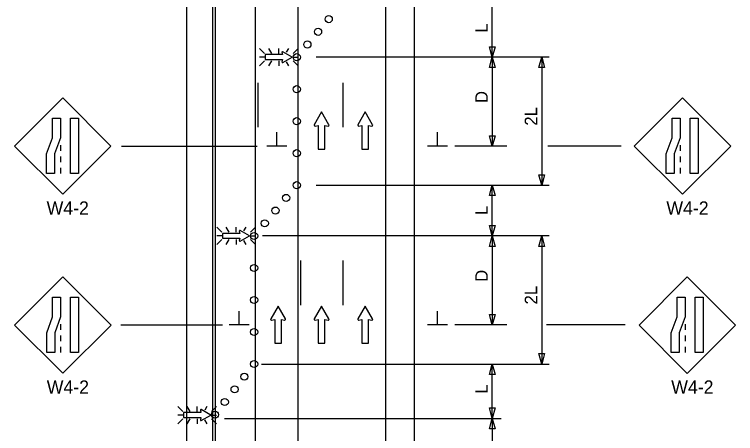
# Model space of a CAD drawing. Extents: x 16726 to 18475, y 5752 to 6929.
# Drawn here: x 16770.6 to 17176.3, y 6401.3 to 6637.1 of the extents above; entities that cross this region are included whole.
import ezdxf

# ---------------------------------------------------------------- set-up
doc = ezdxf.new("R2010")
doc.units = 0
for name, color, linetype in [('ALI_LEGAL_EX', 7, 'Continuous'), ('MT_SCRATCH_LEVEL_E', 7, 'Continuous'), ('PAVT_EDGE_EX', 7, 'Continuous'), ('TRAFFIC_SIGNS_PR', 7, 'Continuous'), ('TYPICAL_TEXT_DIMEN_PR', 7, 'Continuous')]:
    doc.layers.add(name, color=color, linetype=linetype)

msp = doc.modelspace()

# ---------------------------------------------------------------- linework, layer by layer
at = {"layer": 'ALI_LEGAL_EX'}
for p, q in [((16881.97, 6876.43), (16881.97, 5996.39)), ((16905.97, 6876.43), (16905.97, 5996.39)), ((16929.97, 6876.43), (16929.97, 5996.39))]:
    msp.add_line(p, q, dxfattribs=at)
for points in [[(16907.45, 6598.64), (16907.45, 6573.64)], [(16955.45, 6598.64), (16955.45, 6573.64)], [(16931.45, 6498.64), (16931.45, 6473.64)], [(16955.45, 6498.64), (16955.45, 6473.64)]]:
    msp.add_lwpolyline(points, dxfattribs=at)
at = {"layer": 'MT_SCRATCH_LEVEL_E'}
for p, q in [((16943.41, 6582.24), (16939.3, 6575)), ((16947.56, 6575), (16943.41, 6582.24)), ((16967.97, 6582.24), (16963.86, 6575)), ((16972.12, 6575), (16967.97, 6582.24)), ((16939.79, 6574.31), (16941.56, 6574.63)), ((16941.56, 6574.63), (16941.56, 6561.37)), ((16945.3, 6561.37), (16945.3, 6574.63)), ((16945.3, 6574.63), (16947.08, 6574.31)), ((16964.34, 6574.31), (16966.12, 6574.63)), ((16966.12, 6574.63), (16966.12, 6561.37)), ((16969.86, 6561.37), (16969.86, 6574.63)), ((16969.86, 6574.63), (16971.64, 6574.31)), ((16941.56, 6561.37), (16945.3, 6561.37)), ((16966.12, 6561.37), (16969.86, 6561.37)), ((16918.89, 6473.07), (16914.77, 6465.83)), ((16923.03, 6465.83), (16918.89, 6473.07)), ((16943.41, 6473.07), (16939.3, 6465.83)), ((16947.56, 6465.83), (16943.41, 6473.07)), ((16967.97, 6473.07), (16963.86, 6465.83)), ((16972.12, 6465.83), (16967.97, 6473.07)), ((16915.26, 6465.15), (16917.03, 6465.46)), ((16917.03, 6465.46), (16917.03, 6452.2)), ((16920.78, 6452.2), (16920.78, 6465.46)), ((16920.78, 6465.46), (16922.55, 6465.15)), ((16939.79, 6465.15), (16941.56, 6465.46)), ((16941.56, 6465.46), (16941.56, 6452.2)), ((16945.3, 6452.2), (16945.3, 6465.46)), ((16945.3, 6465.46), (16947.08, 6465.15)), ((16964.34, 6465.15), (16966.12, 6465.46)), ((16966.12, 6465.46), (16966.12, 6452.2)), ((16969.86, 6452.2), (16969.86, 6465.46)), ((16969.86, 6465.46), (16971.64, 6465.15)), ((16917.03, 6452.2), (16920.78, 6452.2)), ((16941.56, 6452.2), (16945.3, 6452.2)), ((16966.12, 6452.2), (16969.86, 6452.2))]:
    msp.add_line(p, q, dxfattribs=at)
for centre, start, end in [((16939.71, 6574.77), 150.4248, 279.9638), ((16947.15, 6574.77), 260.0362, 29.7731), ((16964.27, 6574.77), 150.4248, 279.9638), ((16971.71, 6574.77), 260.0362, 29.7731), ((16915.18, 6465.6), 150.4248, 279.9638), ((16922.62, 6465.61), 260.0362, 29.7731), ((16939.71, 6465.6), 150.4248, 279.9638), ((16947.15, 6465.61), 260.0362, 29.7731), ((16964.27, 6465.6), 150.4248, 279.9638), ((16971.71, 6465.61), 260.0362, 29.7731)]:
    msp.add_arc(centre, 0.463, start, end, dxfattribs=at)
at = {"layer": 'PAVT_EDGE_EX'}
for p, q in [((16867.45, 6928.88), (16867.45, 6018.6)), ((16883.45, 6928.88), (16883.45, 6018.6)), ((16979.45, 6928.88), (16979.45, 6018.6)), ((16995.45, 6928.88), (16995.45, 6018.6))]:
    msp.add_line(p, q, dxfattribs=at)
at = {"layer": 'TRAFFIC_SIGNS_PR'}
for p, q in [((16911.22, 6615.13), (16908.4, 6617.95)), ((16913.52, 6617.95), (16915.15, 6615.13)), ((16919.31, 6615.13), (16919.31, 6617.95)), ((16924.78, 6617.95), (16923.57, 6615.86)), ((16930.21, 6617.95), (16927.39, 6615.13)), ((16911.22, 6613.1), (16908.4, 6613.1)), ((16927.39, 6613.1), (16930.21, 6613.1)), ((16911.22, 6611.07), (16908.4, 6608.25)), ((16915.17, 6611.07), (16913.54, 6608.25)), ((16919.31, 6611.07), (16919.31, 6608.25)), ((16923.49, 6610.43), (16924.75, 6608.25)), ((16930.21, 6608.25), (16927.39, 6611.07)), ((16797.77, 6590.23), (16770.62, 6563.08)), ((16824.92, 6563.08), (16797.77, 6590.23)), ((17146.4, 6590.23), (17119.25, 6563.08)), ((17173.55, 6563.08), (17146.4, 6590.23)), ((16770.62, 6563.08), (16797.77, 6535.92)), ((16796.52, 6563.57), (16796.52, 6560.37)), ((16797.77, 6535.92), (16824.92, 6563.08)), ((17119.25, 6563.08), (17146.4, 6535.92)), ((17145.15, 6563.57), (17145.15, 6560.37)), ((17146.4, 6535.92), (17173.55, 6563.08)), ((16796.52, 6557.17), (16796.52, 6553.97)), ((17145.15, 6557.17), (17145.15, 6553.97)), ((16796.52, 6550.77), (16796.52, 6547.57)), ((17145.15, 6550.77), (17145.15, 6547.57)), ((16887.22, 6514.57), (16884.4, 6517.39)), ((16889.52, 6517.39), (16891.15, 6514.57)), ((16895.31, 6514.57), (16895.31, 6517.39)), ((16900.78, 6517.39), (16899.57, 6515.3)), ((16906.21, 6517.39), (16903.39, 6514.57)), ((16887.22, 6512.54), (16884.4, 6512.54)), ((16903.39, 6512.54), (16906.21, 6512.54)), ((16887.22, 6510.51), (16884.4, 6507.69)), ((16891.17, 6510.51), (16889.54, 6507.69)), ((16895.31, 6510.51), (16895.31, 6507.69)), ((16899.49, 6509.87), (16900.75, 6507.69)), ((16906.21, 6507.69), (16903.39, 6510.51)), ((16797.85, 6489.53), (16770.69, 6462.38)), ((16825, 6462.38), (16797.85, 6489.53)), ((17149.14, 6489.52), (17121.98, 6462.37)), ((17176.29, 6462.37), (17149.14, 6489.52)), ((16770.69, 6462.38), (16797.85, 6435.23)), ((16796.6, 6462.87), (16796.6, 6459.67)), ((16797.85, 6435.23), (16825, 6462.38)), ((17121.98, 6462.37), (17149.14, 6435.21)), ((17147.89, 6462.86), (17147.89, 6459.66)), ((17149.14, 6435.21), (17176.29, 6462.37)), ((16796.6, 6456.47), (16796.6, 6453.27)), ((17147.89, 6456.46), (17147.89, 6453.26)), ((16796.6, 6450.07), (16796.6, 6446.87)), ((17147.89, 6450.06), (17147.89, 6446.86)), ((16865.3, 6413.78), (16862.48, 6416.6)), ((16867.6, 6416.6), (16869.23, 6413.78)), ((16873.39, 6413.78), (16873.39, 6416.6)), ((16878.85, 6416.6), (16877.65, 6414.51)), ((16884.29, 6416.6), (16881.47, 6413.78)), ((16865.3, 6411.75), (16862.48, 6411.75)), ((16865.3, 6409.72), (16862.48, 6406.89)), ((16869.25, 6409.72), (16867.62, 6406.9)), ((16873.39, 6409.72), (16873.39, 6406.9)), ((16881.47, 6411.75), (16884.29, 6411.75)), ((16884.29, 6406.9), (16881.47, 6409.72)), ((16877.57, 6409.08), (16878.83, 6406.9))]:
    msp.add_line(p, q, dxfattribs=at)
for points in [[(16921.13, 6615.78), (16921.36, 6614.49), (16911.64, 6614.49), (16911.64, 6611.74), (16921.36, 6611.74), (16921.13, 6610.44)], [(16921.63, 6610.09), (16926.94, 6613.1), (16921.63, 6616.14)], [(16897.13, 6515.22), (16897.36, 6513.92), (16887.64, 6513.92), (16887.64, 6511.18), (16897.36, 6511.18), (16897.13, 6509.88)], [(16897.63, 6509.52), (16902.94, 6512.54), (16897.63, 6515.58)], [(16875.21, 6414.43), (16875.44, 6413.13), (16865.72, 6413.13), (16865.72, 6410.39), (16875.44, 6410.39), (16875.21, 6409.09)], [(16875.71, 6408.73), (16881.02, 6411.75), (16875.71, 6414.79)]]:
    msp.add_lwpolyline(points, dxfattribs=at)
for points in [[(16796.52, 6578.81), (16796.52, 6567.63), (16793.18, 6558.75), (16793.18, 6547.57), (16788.68, 6547.57), (16788.68, 6558.75), (16792.03, 6567.63), (16792.03, 6578.81)], [(16806.66, 6578.81), (16806.66, 6547.57), (16802.16, 6547.57), (16802.16, 6578.81)], [(17145.15, 6578.81), (17145.15, 6567.63), (17141.81, 6558.75), (17141.81, 6547.57), (17137.31, 6547.57), (17137.31, 6558.75), (17140.66, 6567.63), (17140.66, 6578.81)], [(17155.29, 6578.81), (17155.29, 6547.57), (17150.8, 6547.57), (17150.8, 6578.81)], [(16796.6, 6478.12), (16796.6, 6466.93), (16793.26, 6458.05), (16793.26, 6446.87), (16788.76, 6446.87), (16788.76, 6458.05), (16792.11, 6466.93), (16792.11, 6478.12)], [(16806.74, 6478.12), (16806.74, 6446.87), (16802.24, 6446.87), (16802.24, 6478.12)], [(17147.89, 6478.1), (17147.89, 6466.92), (17144.54, 6458.04), (17144.54, 6446.86), (17140.05, 6446.86), (17140.05, 6458.04), (17143.4, 6466.92), (17143.4, 6478.1)], [(17158.02, 6478.1), (17158.02, 6446.86), (17153.53, 6446.86), (17153.53, 6478.1)]]:
    msp.add_lwpolyline(points, close=True, dxfattribs=at)
for centre in [(16947.45, 6634.45), (16941.45, 6627.31), (16935.45, 6620.17), (16929.45, 6613.03), (16929.45, 6595.03), (16929.45, 6577.03), (16929.45, 6559.03), (16929.45, 6541.03), (16923.45, 6533.89), (16917.45, 6526.75), (16911.45, 6519.61), (16905.45, 6512.47), (16905.45, 6494.47), (16905.45, 6476.47), (16905.45, 6458.47), (16905.45, 6440.47), (16899.95, 6433.33), (16894.45, 6426.21), (16888.95, 6419.08), (16883.46, 6411.96)]:
    msp.add_circle(centre, 2, dxfattribs=at)
for centre, start, end in [((16921.47, 6615.84), 61.4833, 189.9593), ((16921.47, 6610.39), 170.7308, 298.8916), ((16897.47, 6515.28), 61.4833, 189.9593), ((16897.47, 6509.82), 170.7308, 298.8916), ((16875.55, 6414.49), 61.4833, 189.9593), ((16875.55, 6409.03), 170.7308, 298.8916)]:
    msp.add_arc(centre, 0.341, start, end, dxfattribs=at)
at = {"layer": 'TYPICAL_TEXT_DIMEN_PR'}
for p, q in [((17039.45, 6613.03), (17039.45, 6643.59)), ((17039.45, 6613.03), (17037.88, 6618.89)), ((17037.88, 6618.89), (17039.45, 6618.89)), ((17039.45, 6618.89), (17041.02, 6618.89)), ((17041.02, 6618.89), (17039.45, 6613.03)), ((17071.49, 6613.03), (16940.35, 6613.03)), ((17037.88, 6607.17), (17039.45, 6613.03)), ((17039.45, 6613.03), (17039.45, 6563.03)), ((17039.45, 6613.03), (17041.02, 6607.17)), ((17065.68, 6607.17), (17067.25, 6613.03)), ((17067.25, 6613.03), (17068.82, 6607.17)), ((17067.25, 6613.03), (17067.25, 6541.03)), ((17039.45, 6607.17), (17037.88, 6607.17)), ((17041.02, 6607.17), (17039.45, 6607.17)), ((17067.25, 6607.17), (17065.68, 6607.17)), ((17068.82, 6607.17), (17067.25, 6607.17)), ((16918.24, 6563.03), (16918.24, 6570.82)), ((17008.57, 6563.03), (17008.57, 6570.82)), ((17039.45, 6563.03), (17037.88, 6568.89)), ((17037.88, 6568.89), (17039.45, 6568.89)), ((17039.45, 6568.89), (17041.02, 6568.89)), ((17041.02, 6568.89), (17039.45, 6563.03)), ((17067.25, 6567.9), (17067.25, 6564.13)), ((16830.86, 6563.03), (16907.2, 6563.03)), ((16923.87, 6563.03), (16912.62, 6563.03)), ((17014.2, 6563.03), (17002.95, 6563.03)), ((17047.58, 6563.03), (17018.45, 6563.03)), ((17112, 6563.03), (17070.65, 6563.03)), ((17067.25, 6541.03), (17065.68, 6546.89)), ((17065.68, 6546.89), (17067.25, 6546.89)), ((17067.25, 6546.89), (17068.82, 6546.89)), ((17068.82, 6546.89), (17067.25, 6541.03)), ((16940.35, 6541.03), (17071.49, 6541.03)), ((17037.88, 6535.17), (17039.45, 6541.03)), ((17039.45, 6512.47), (17039.45, 6541.03)), ((17039.45, 6541.03), (17041.02, 6535.17)), ((17039.45, 6535.17), (17037.88, 6535.17)), ((17041.02, 6535.17), (17039.45, 6535.17)), ((17039.45, 6512.47), (17037.88, 6518.33)), ((17037.88, 6518.33), (17039.45, 6518.33)), ((17039.45, 6518.33), (17041.02, 6518.33)), ((17041.02, 6518.33), (17039.45, 6512.47)), ((17071.49, 6512.47), (16910.16, 6512.47)), ((17037.88, 6506.61), (17039.45, 6512.47)), ((17039.45, 6512.47), (17039.45, 6462.47)), ((17039.45, 6512.47), (17041.02, 6506.61)), ((17065.68, 6506.61), (17067.25, 6512.47)), ((17067.25, 6512.47), (17068.82, 6506.61)), ((17067.25, 6512.47), (17067.25, 6440.47)), ((17039.45, 6506.61), (17037.88, 6506.61)), ((17041.02, 6506.61), (17039.45, 6506.61)), ((17067.25, 6506.61), (17065.68, 6506.61)), ((17068.82, 6506.61), (17067.25, 6506.61)), ((16897.08, 6462.47), (16897.08, 6470.25)), ((17008.57, 6462.47), (17008.57, 6470.25)), ((17039.45, 6462.47), (17037.88, 6468.33)), ((17037.88, 6468.33), (17039.45, 6468.33)), ((17039.45, 6468.33), (17041.02, 6468.33)), ((17041.02, 6468.33), (17039.45, 6462.47)), ((17067.25, 6467.34), (17067.25, 6463.57)), ((16830.5, 6462.47), (16887.64, 6462.47)), ((16902.71, 6462.47), (16891.46, 6462.47)), ((17014.2, 6462.47), (17002.95, 6462.47)), ((17047.58, 6462.47), (17018.45, 6462.47)), ((17114.15, 6462.47), (17069.93, 6462.47)), ((17067.25, 6440.47), (17065.68, 6446.33)), ((17065.68, 6446.33), (17067.25, 6446.33)), ((17067.25, 6446.33), (17068.82, 6446.33)), ((17068.82, 6446.33), (17067.25, 6440.47)), ((16909.63, 6440.47), (17071.49, 6440.47)), ((17037.88, 6434.61), (17039.45, 6440.47)), ((17039.45, 6409.9), (17039.45, 6440.47)), ((17039.45, 6440.47), (17041.02, 6434.61)), ((17039.45, 6434.61), (17037.88, 6434.61)), ((17041.02, 6434.61), (17039.45, 6434.61)), ((17039.45, 6409.9), (17037.88, 6415.77)), ((17037.88, 6415.77), (17039.45, 6415.77)), ((17039.45, 6415.77), (17041.02, 6415.77)), ((17041.02, 6415.77), (17039.45, 6409.9)), ((16888.76, 6409.9), (17044.45, 6409.9)), ((17037.88, 6404.04), (17039.45, 6409.9)), ((17039.45, 6409.9), (17039.45, 6369.9)), ((17039.45, 6409.9), (17041.02, 6404.04)), ((17039.45, 6404.04), (17037.88, 6404.04)), ((17041.02, 6404.04), (17039.45, 6404.04))]:
    msp.add_line(p, q, dxfattribs=at)

# ---------------------------------------------------------------- texts
at = {"layer": 'TRAFFIC_SIGNS_PR'}
for p in [(16788.73, 6524.49), (17137.36, 6524.49), (16788.8, 6423.79), (17140.09, 6423.78)]:
    msp.add_text('W4-2', height=7.44, dxfattribs=at).set_placement(p)
at = {"layer": 'TYPICAL_TEXT_DIMEN_PR'}
for s, p in [('L', (17036.89, 6626.89)), ('D', (17036.89, 6587.25)), ('2L', (17064.69, 6574.53)), ('L', (17036.89, 6524.32)), ('D', (17036.89, 6486.69)), ('2L', (17064.69, 6473.97)), ('L', (17036.89, 6423.76))]:
    msp.add_text(s, height=7, rotation=90, dxfattribs=at).set_placement(p)

doc.saveas('drawing.dxf')
